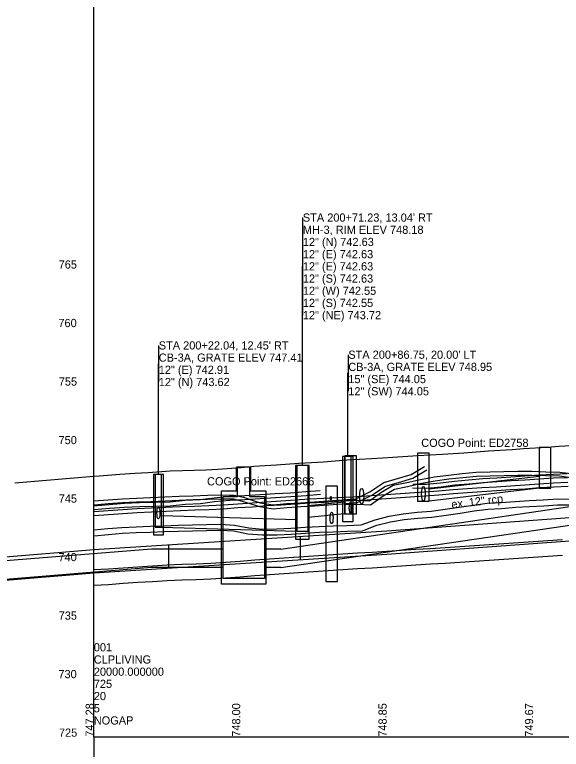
# Model space of a CAD drawing. Extents: x 1833473 to 1837132, y 704683 to 706683.
# Drawn here: x 1833683.8 to 1833870.4, y 705678.3 to 705929.4 of the extents above; entities that cross this region are included whole.
import ezdxf

# ---------------------------------------------------------------- set-up
doc = ezdxf.new("R2010")
doc.units = 0
for name, color, linetype in [('DR_P_Text', 7, 'Continuous'), ('DR_X_Cells', 7, 'Continuous'), ('DR_X_Storm_Sewer', 7, 'Continuous'), ('DR_X_Text', 7, 'Continuous'), ('GK_Cells', 7, 'Continuous'), ('PF_P_Sta_Elev_Text', 7, 'Continuous'), ('PF_X_Ground_Line', 7, 'Continuous'), ('PF_X_Text', 7, 'Continuous'), ('SC_Scratch1', 7, 'Continuous'), ('UT_P_Electric', 7, 'Continuous'), ('UT_P_Telecom', 7, 'Continuous'), ('UT_X_Electric', 7, 'Continuous'), ('UT_X_Gas', 7, 'Continuous'), ('UT_X_Telecom', 7, 'Continuous'), ('UT_X_Water', 7, 'Continuous')]:
    doc.layers.add(name, color=color, linetype=linetype)

msp = doc.modelspace()

# ---------------------------------------------------------------- linework, layer by layer
at = {"layer": 'DR_P_Text'}
for p, q in [((1833782.08, 705860.09), (1833782.08, 705826.75)), ((1833732.89, 705816.39), (1833732.89, 705803.89)), ((1833797.6, 705813.22), (1833797.6, 705800.72))]:
    msp.add_line(p, q, dxfattribs=at)
for points in [[(1833782.01, 705775.37), (1833782.01, 705843.42), (1833782.08, 705843.42)], [(1833732.82, 705772.29), (1833732.82, 705810.14), (1833732.89, 705810.14)], [(1833797.53, 705778.45), (1833797.53, 705806.97), (1833797.6, 705806.97)]]:
    msp.add_lwpolyline(points, dxfattribs=at)
at = {"layer": 'DR_X_Cells'}
for points in [[(1833710.78, 705739.75), (1833715.78, 705740.07), (1833720.78, 705740.42), (1833725.78, 705740.76), (1833730.78, 705741.03), (1833735.78, 705741.41), (1833740.78, 705741.61), (1833745.78, 705741.74), (1833750.78, 705741.96), (1833755.78, 705742.33), (1833760.78, 705742.66), (1833765.78, 705743.09), (1833770.78, 705743.4), (1833775.78, 705743.75), (1833780.78, 705744.16), (1833785.78, 705744.47), (1833790.78, 705744.76), (1833795.78, 705745.13), (1833800.78, 705745.45), (1833805.78, 705745.73), (1833810.78, 705746.06), (1833815.78, 705746.39), (1833820.78, 705746.73), (1833825.78, 705747.03), (1833830.78, 705747.32), (1833835.78, 705747.62), (1833840.78, 705747.97), (1833845.78, 705748.35), (1833850.78, 705748.67), (1833855.78, 705749.01), (1833860.78, 705749.34), (1833865.78, 705749.67), (1833870.78, 705750.02)], [(1833710.78, 705734.42), (1833715.78, 705734.73), (1833720.78, 705735.08), (1833725.78, 705735.43), (1833730.78, 705735.7), (1833735.78, 705736.08), (1833740.78, 705736.28), (1833745.78, 705736.41), (1833750.78, 705736.63), (1833755.78, 705737), (1833760.78, 705737.33), (1833765.78, 705737.76), (1833770.78, 705738.06), (1833775.78, 705738.42), (1833780.78, 705738.82), (1833785.78, 705739.13), (1833790.78, 705739.43), (1833795.78, 705739.8), (1833800.78, 705740.11), (1833805.78, 705740.4), (1833810.78, 705740.73), (1833815.78, 705741.05), (1833820.78, 705741.39), (1833825.78, 705741.7), (1833830.78, 705741.99), (1833835.78, 705742.28), (1833840.78, 705742.64), (1833845.78, 705743.01), (1833850.78, 705743.34), (1833855.78, 705743.67), (1833860.78, 705744.01), (1833865.78, 705744.34), (1833870.78, 705744.69)]]:
    msp.add_lwpolyline(points, dxfattribs=at)
at = {"layer": 'DR_X_Storm_Sewer'}
for p, q in [((1833862.86, 705771.6), (1833825.3, 705767.24)), ((1833862.86, 705767.57), (1833825.3, 705763.21)), ((1833796.4, 705762.85), (1833783.96, 705761.53)), ((1833796.4, 705758.85), (1833783.96, 705757.53)), ((1833733.88, 705758.29), (1833780.06, 705756.85)), ((1833733.88, 705754.29), (1833780.06, 705752.85))]:
    msp.add_line(p, q, dxfattribs=at)
for points in [[(1833864.86, 705781.49), (1833862.86, 705781.49), (1833862.86, 705767.57), (1833866.86, 705767.57), (1833866.86, 705781.49), (1833864.86, 705781.49)], [(1833798.51, 705778.69), (1833796.51, 705778.69), (1833796.51, 705758.85), (1833800.51, 705758.85), (1833800.51, 705778.69), (1833798.51, 705778.69)], [(1833823.3, 705779.61), (1833821.3, 705779.61), (1833821.3, 705763.21), (1833825.3, 705763.21), (1833825.3, 705779.61), (1833823.3, 705779.61)], [(1833795.71, 705778.45), (1833795.71, 705756.18), (1833799.35, 705756.18), (1833799.35, 705778.45), (1833795.71, 705778.45)], [(1833796.4, 705778.45), (1833796.4, 705758.85), (1833798.66, 705758.85), (1833798.66, 705778.45)], [(1833779.65, 705775.37), (1833779.65, 705750.18), (1833784.36, 705750.18), (1833784.36, 705775.37), (1833779.65, 705775.37)], [(1833780.06, 705775.37), (1833780.06, 705752.85), (1833783.96, 705752.85), (1833783.96, 705775.37)], [(1833731.11, 705772.29), (1833731.11, 705751.62), (1833734.53, 705751.62), (1833734.53, 705772.29), (1833731.11, 705772.29)], [(1833731.76, 705772.29), (1833731.76, 705754.29), (1833733.88, 705754.29), (1833733.88, 705772.29)], [(1833791.98, 705768.33), (1833789.98, 705768.33), (1833789.98, 705735.73), (1833793.98, 705735.73), (1833793.98, 705768.33), (1833791.98, 705768.33)]]:
    msp.add_lwpolyline(points, dxfattribs=at)
for centre, major_axis in [((1833823.3, 705765.71), (0, 2.5)), ((1833732.82, 705759.13), (0, 2)), ((1833798.51, 705760.85), (0, 2)), ((1833791.98, 705757.45), (0, 2))]:
    msp.add_ellipse(centre, major_axis=major_axis, ratio=0.25, dxfattribs=at)
at = {"layer": 'GK_Cells'}
for q in [(1833710.78, 706682.65), (1833710.78, 706682.65), (1834910.78, 705682.65), (1833710.78, 704682.65), (1834910.78, 705682.65), (1833710.78, 704682.65)]:
    msp.add_line((1833710.78, 705682.65), q, dxfattribs=at)
at = {"layer": 'PF_X_Ground_Line'}
for points in [[(1833710.78, 705771.75), (1833712.71, 705771.85), (1833719.7, 705772.34), (1833724.79, 705772.71), (1833729.35, 705772.92), (1833736.91, 705773.5), (1833741.07, 705773.62), (1833749.02, 705773.82), (1833753.14, 705774.15), (1833761.12, 705774.68), (1833765.46, 705775.07), (1833773.13, 705775.54), (1833780.83, 705776.16), (1833785.14, 705776.43), (1833789.25, 705776.65), (1833797.22, 705777.24), (1833805.57, 705777.72), (1833809.29, 705777.97), (1833812.93, 705778.19), (1833821.36, 705778.77), (1833829.83, 705779.27), (1833833.43, 705779.47), (1833837.12, 705779.7), (1833845.5, 705780.33), (1833853.59, 705780.86), (1833857.54, 705781.13), (1833865.57, 705781.66), (1833869.59, 705781.93), (1833873.66, 705782.23)], [(1833683.78, 705769.38), (1833710.78, 705771.75)]]:
    msp.add_lwpolyline(points, dxfattribs=at)
at = {"layer": 'UT_P_Electric'}
for p, q in [((1833759.52, 705766.74), (1833759.52, 705774.74)), ((1833764.44, 705774.74), (1833759.52, 705774.74)), ((1833759.85, 705764.74), (1833759.85, 705774.74)), ((1833764.1, 705764.74), (1833764.1, 705774.74)), ((1833764.44, 705766.74), (1833764.44, 705774.74)), ((1833774.58, 705746.77), (1833933.33, 705770.22)), ((1833754.43, 705734.74), (1833754.43, 705766.74)), ((1833754.43, 705766.74), (1833759.85, 705766.74)), ((1833764.1, 705766.74), (1833769.52, 705766.74)), ((1833769.52, 705766.74), (1833769.52, 705734.74)), ((1833754.93, 705736.74), (1833754.93, 705764.74)), ((1833754.93, 705764.74), (1833759.85, 705764.74)), ((1833764.1, 705764.74), (1833769.02, 705764.74)), ((1833769.02, 705764.74), (1833769.02, 705736.74)), ((1833774.58, 705740.44), (1833933.33, 705763.89)), ((1833730.43, 705746.77), (1833535.78, 705730.98)), ((1833754.93, 705746.77), (1833730.43, 705746.77)), ((1833774.58, 705746.77), (1833769.02, 705746.77)), ((1833730.43, 705740.44), (1833535.78, 705724.65)), ((1833754.93, 705740.44), (1833730.43, 705740.44)), ((1833774.58, 705740.44), (1833769.02, 705740.44)), ((1833769.02, 705736.74), (1833754.93, 705736.74)), ((1833769.52, 705734.74), (1833754.43, 705734.74))]:
    msp.add_line(p, q, dxfattribs=at)
at = {"layer": 'UT_P_Telecom'}
for p, q in [((1833781.24, 705751.13), (1833781.24, 705743.13)), ((1833486.78, 705728.42), (1833710.78, 705746.64)), ((1833736.3, 705748.27), (1833736.3, 705740.27)), ((1833486.78, 705720.42), (1833710.78, 705738.64))]:
    msp.add_line(p, q, dxfattribs=at)
for points in [[(1833710.78, 705746.64), (1833810.78, 705753.01), (1833910.78, 705760.34)], [(1833710.78, 705738.64), (1833810.78, 705745.01), (1833910.78, 705752.34)]]:
    msp.add_lwpolyline(points, dxfattribs=at)
at = {"layer": 'UT_X_Electric'}
for points in [[(1833796.23, 705763.48), (1833800.89, 705763.47), (1833804.87, 705763.29), (1833808.82, 705766.14), (1833812.94, 705768.57), (1833817.61, 705769.51), (1833822.35, 705770.6), (1833827.09, 705771.46), (1833831.84, 705772.07), (1833836.59, 705772.61), (1833841.33, 705773.07), (1833846.07, 705773.13), (1833850.82, 705773.27), (1833855.57, 705773.41), (1833860.33, 705773.39), (1833865.09, 705773.24), (1833869.86, 705773.09), (1833874.63, 705772.5)], [(1833796.23, 705762.15), (1833800.86, 705762.14), (1833805.28, 705761.94), (1833809.55, 705765.03), (1833813.42, 705767.31), (1833817.89, 705768.21), (1833822.62, 705769.3), (1833827.29, 705770.15), (1833832, 705770.75), (1833836.73, 705771.29), (1833841.41, 705771.74), (1833846.1, 705771.8), (1833850.86, 705771.94), (1833855.59, 705772.07), (1833860.31, 705772.06), (1833865.05, 705771.91), (1833869.76, 705771.76), (1833874.42, 705771.18)], [(1833710.78, 705761.62), (1833716, 705762.07), (1833721.22, 705762.45), (1833726.42, 705762.68), (1833731.61, 705762.79), (1833736.79, 705762.95), (1833741.95, 705763.48), (1833747.09, 705763.73), (1833751.9, 705764.33), (1833757.11, 705764.82), (1833762.32, 705765.11), (1833767.53, 705765.43), (1833772.74, 705765.75), (1833777.94, 705766.05), (1833783.14, 705766.45), (1833788.1, 705766.85)], [(1833710.89, 705760.29), (1833716.11, 705760.74), (1833721.29, 705761.12), (1833726.46, 705761.34), (1833731.64, 705761.45), (1833736.87, 705761.62), (1833742.05, 705762.15), (1833747.21, 705762.41), (1833752.04, 705763), (1833757.21, 705763.49), (1833762.4, 705763.78), (1833767.61, 705764.1), (1833772.82, 705764.42), (1833778.03, 705764.72), (1833783.25, 705765.12), (1833788.2, 705765.52)]]:
    msp.add_lwpolyline(points, dxfattribs=at)
msp.add_ellipse((1833791.74, 705764.17), major_axis=(0, -0.667), ratio=0.25, dxfattribs=at)
at = {"layer": 'UT_X_Gas'}
for points in [[(1833710.78, 705763.23), (1833715.63, 705763.63), (1833720.48, 705763.98), (1833725.33, 705764.23), (1833730.18, 705764.4), (1833735.03, 705764.6), (1833739.87, 705764.87), (1833744.72, 705765.03), (1833749.56, 705765.2), (1833754.4, 705765.32), (1833758.69, 705765.23), (1833761.85, 705764.49), (1833764.86, 705763.5), (1833767.62, 705762.6), (1833772.03, 705761.93), (1833776.72, 705762.31), (1833781.41, 705762.64), (1833786.13, 705762.95), (1833790.84, 705763.27), (1833795.56, 705763.59), (1833800.29, 705763.97), (1833805.04, 705766.39), (1833809.75, 705769.57), (1833814.46, 705770.85), (1833819.15, 705772.24), (1833823.74, 705775.04)], [(1833710.89, 705761.9), (1833715.73, 705762.31), (1833720.57, 705762.65), (1833725.39, 705762.9), (1833730.23, 705763.07), (1833735.09, 705763.27), (1833739.93, 705763.54), (1833744.76, 705763.7), (1833749.6, 705763.87), (1833754.4, 705763.99), (1833758.52, 705763.9), (1833761.48, 705763.21), (1833764.45, 705762.23), (1833767.32, 705761.3), (1833771.98, 705760.59), (1833776.82, 705760.98), (1833781.5, 705761.31), (1833786.22, 705761.62), (1833790.93, 705761.94), (1833795.66, 705762.26), (1833800.66, 705762.66), (1833805.71, 705765.24), (1833810.32, 705768.34), (1833814.82, 705769.57), (1833819.7, 705771.01), (1833824.43, 705773.9)], [(1833819.64, 705767.67), (1833824.47, 705767.62), (1833829.32, 705768.11), (1833834.09, 705768.69), (1833838.87, 705769.11), (1833843.65, 705769.57), (1833848.44, 705769.84), (1833853.25, 705770.17), (1833858.07, 705770.45), (1833862.89, 705770.83), (1833867.68, 705771.09), (1833872.48, 705771.26)], [(1833819.65, 705769), (1833824.41, 705768.95), (1833829.17, 705769.44), (1833833.95, 705770.01), (1833838.75, 705770.43), (1833843.55, 705770.9), (1833848.35, 705771.17), (1833853.16, 705771.5), (1833857.98, 705771.78), (1833862.8, 705772.16), (1833867.62, 705772.42), (1833872.44, 705772.59)]]:
    msp.add_lwpolyline(points, dxfattribs=at)
msp.add_ellipse((1833802.25, 705764.86), major_axis=(0, -2.67), ratio=0.250001, dxfattribs=at)
at = {"layer": 'UT_X_Telecom'}
for points in [[(1833710.78, 705759.64), (1833715.7, 705759.98), (1833720.62, 705760.33), (1833725.54, 705760.65), (1833730.46, 705760.85), (1833735.37, 705761.09), (1833740.29, 705761.34), (1833745.2, 705761.48), (1833750.11, 705761.64), (1833755.01, 705761.92), (1833759.91, 705762.27), (1833764.82, 705762.55), (1833769.73, 705762.98), (1833774.64, 705763.28), (1833779.54, 705763.59), (1833784.44, 705763.91), (1833789.34, 705764.2), (1833794.24, 705764.46), (1833799.14, 705764.67), (1833804.03, 705764.96), (1833808.92, 705765.3), (1833813.82, 705765.62), (1833818.72, 705765.98), (1833823.62, 705766.36), (1833828.51, 705766.67), (1833833.41, 705767.12), (1833838.31, 705767.47), (1833843.22, 705767.79), (1833848.12, 705768.11), (1833853.02, 705768.45), (1833857.91, 705768.76), (1833862.82, 705769.11), (1833867.72, 705769.37), (1833872.63, 705769.67)], [(1833710.87, 705758.31), (1833715.79, 705758.65), (1833720.71, 705759), (1833725.61, 705759.32), (1833730.52, 705759.52), (1833735.44, 705759.75), (1833740.34, 705760.01), (1833745.24, 705760.15), (1833750.17, 705760.31), (1833755.09, 705760.59), (1833760, 705760.94), (1833764.92, 705761.22), (1833769.83, 705761.65), (1833774.72, 705761.95), (1833779.63, 705762.26), (1833784.53, 705762.58), (1833789.42, 705762.87), (1833794.3, 705763.12), (1833799.21, 705763.34), (1833804.11, 705763.63), (1833809.01, 705763.97), (1833813.91, 705764.29), (1833818.82, 705764.65), (1833823.71, 705765.03), (1833828.62, 705765.34), (1833833.52, 705765.79), (1833838.4, 705766.14), (1833843.3, 705766.46), (1833848.21, 705766.78), (1833853.1, 705767.12), (1833858, 705767.43), (1833862.9, 705767.78), (1833867.8, 705768.04), (1833872.72, 705768.34)]]:
    msp.add_lwpolyline(points, dxfattribs=at)
at = {"layer": 'UT_X_Water'}
for points in [[(1833710.78, 705753.34), (1833715.59, 705753.77), (1833720.4, 705754.19), (1833725.21, 705754.44), (1833730.02, 705754.58), (1833734.83, 705754.76), (1833739.64, 705754.92), (1833744.44, 705755.07), (1833749.25, 705755.18), (1833754.06, 705755.25), (1833758.86, 705755), (1833763.67, 705753.99), (1833768.47, 705753.6), (1833773.28, 705753.7), (1833778.08, 705753.92), (1833782.89, 705754.23), (1833787.69, 705754.5), (1833792.49, 705754.69), (1833797.29, 705754.85), (1833802.08, 705755.06), (1833806.87, 705756.82), (1833811.64, 705757.99), (1833816.4, 705758.88), (1833821.19, 705759.4), (1833825.97, 705759.7), (1833830.76, 705760.4), (1833835.54, 705761.06), (1833840.33, 705761.81), (1833845.11, 705762.45), (1833849.9, 705762.67), (1833854.68, 705763.1), (1833859.47, 705763.37), (1833864.25, 705763.61), (1833869.04, 705763.93), (1833873.82, 705763.87)], [(1833710.95, 705751.35), (1833715.77, 705751.77), (1833720.54, 705752.19), (1833725.29, 705752.44), (1833730.08, 705752.58), (1833734.9, 705752.76), (1833739.7, 705752.92), (1833744.5, 705753.07), (1833749.29, 705753.18), (1833754.02, 705753.25), (1833758.61, 705753.01), (1833763.38, 705752.01), (1833768.41, 705751.6), (1833773.34, 705751.7), (1833778.19, 705751.93), (1833783.01, 705752.23), (1833787.79, 705752.51), (1833792.56, 705752.7), (1833797.37, 705752.85), (1833802.48, 705753.07), (1833807.45, 705754.9), (1833812.06, 705756.04), (1833816.69, 705756.9), (1833821.36, 705757.4), (1833826.18, 705757.71), (1833831.04, 705758.42), (1833835.84, 705759.08), (1833840.62, 705759.83), (1833845.29, 705760.45), (1833850.03, 705760.67), (1833854.83, 705761.11), (1833859.57, 705761.37), (1833864.37, 705761.61), (1833869.09, 705761.93), (1833873.68, 705761.87)]]:
    msp.add_lwpolyline(points, dxfattribs=at)

# ---------------------------------------------------------------- texts
at = {"layer": 'DR_P_Text'}
for s, p in [("STA 200+71.23, 13.04' RT", (1833782.15, 705858.69)), ('MH-3, RIM ELEV 748.18', (1833782.15, 705854.52)), ('12" (N) 742.63', (1833782.15, 705850.35)), ('12" (E) 742.63', (1833782.15, 705846.18)), ('12" (E) 742.63', (1833782.15, 705842.02)), ('12" (S) 742.63', (1833782.15, 705837.85)), ('12" (W) 742.55', (1833782.15, 705833.68)), ('12" (S) 742.55', (1833782.15, 705829.52)), ('12" (NE) 743.72', (1833782.15, 705825.35)), ("STA 200+22.04, 12.45' RT", (1833732.96, 705814.99)), ("STA 200+86.75, 20.00' LT", (1833797.67, 705811.82)), ('CB-3A, GRATE ELEV 747.41', (1833732.96, 705810.82)), ('12" (E) 742.91', (1833732.96, 705806.66)), ('CB-3A, GRATE ELEV 748.95', (1833797.67, 705807.65)), ('15" (SE) 744.05', (1833797.67, 705803.49)), ('12" (N) 743.62', (1833732.96, 705802.49)), ('12" (SW) 744.05', (1833797.67, 705799.32))]:
    msp.add_text(s, height=2.8, dxfattribs=at).set_placement(p)
at = {"layer": 'DR_X_Text'}
msp.add_text('ex. 12" rcp', height=2.8, rotation=6.6221, dxfattribs=at).set_placement((1833832.99, 705760.66))
at = {"layer": 'GK_Cells'}
for s, p in [('001', (1833710.78, 705711.82)), ('001', (1833710.78, 705711.82)), ('CLPLIVING', (1833710.78, 705707.65)), ('CLPLIVING', (1833710.78, 705707.65)), ('20000.000000', (1833710.78, 705703.48)), ('20000.000000', (1833710.78, 705703.48)), ('725', (1833710.78, 705699.32)), ('725', (1833710.78, 705699.32)), ('20', (1833710.78, 705695.15)), ('20', (1833710.78, 705695.15)), ('5', (1833710.78, 705690.98)), ('5', (1833710.78, 705690.98)), ('NOGAP', (1833710.78, 705686.82)), ('NOGAP', (1833710.78, 705686.82))]:
    msp.add_text(s, height=2.8, dxfattribs=at).set_placement(p)
at = {"layer": 'PF_P_Sta_Elev_Text'}
for s, p in [('765', (1833698.79, 705842.65)), ('765', (1833698.79, 705842.65)), ('760', (1833698.7, 705822.65)), ('760', (1833698.7, 705822.65)), ('755', (1833698.83, 705802.65)), ('755', (1833698.83, 705802.65)), ('750', (1833698.75, 705782.65)), ('750', (1833698.75, 705782.65)), ('745', (1833698.81, 705762.65)), ('745', (1833698.81, 705762.65)), ('740', (1833698.72, 705742.65)), ('740', (1833698.72, 705742.65)), ('735', (1833698.79, 705722.65)), ('735', (1833698.79, 705722.65)), ('730', (1833698.7, 705702.65)), ('730', (1833698.7, 705702.65)), ('725', (1833698.88, 705682.65)), ('725', (1833698.88, 705682.65))]:
    msp.add_text(s, height=2.8, dxfattribs=at).set_placement(p)
at = {"layer": 'PF_X_Text'}
for s, p in [('747.28', (1833710.78, 705682.65)), ('748.00', (1833760.78, 705682.65)), ('748.85', (1833810.78, 705682.65)), ('749.67', (1833860.78, 705682.65))]:
    msp.add_text(s, height=2.8, rotation=90, dxfattribs=at).set_placement(p)
at = {"layer": 'SC_Scratch1'}
for s, p in [('COGO Point: ED2758', (1833822.57, 705781.7)), ('COGO Point: ED2666', (1833749.44, 705768.54))]:
    msp.add_text(s, height=2.8, dxfattribs=at).set_placement(p)

doc.saveas('drawing.dxf')
